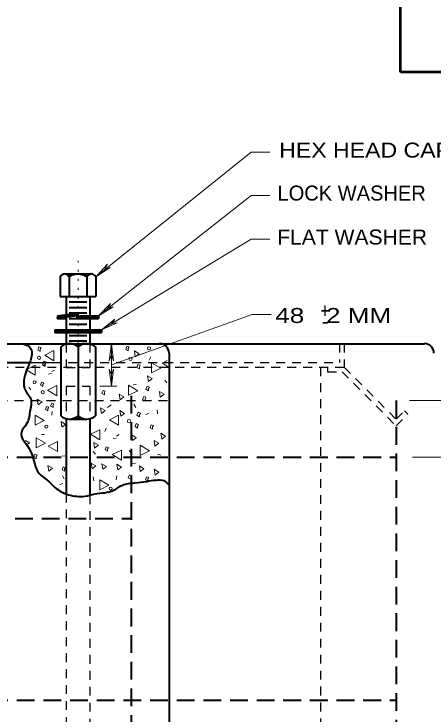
# Model space of a CAD drawing. Extents: x 312583 to 312854, y 144419 to 144597.
# Drawn here: x 312647.35 to 312668.62, y 144453.61 to 144489.11 of the extents above; entities that cross this region are included whole.
import ezdxf

# ---------------------------------------------------------------- set-up
doc = ezdxf.new("R2010")
doc.units = 0
doc.header["$LTSCALE"] = 0.3
for name, pattern in [('DOTTED', [1.5, 0.3, -1.2]), ('MEDIUM_DASHED', [4.5, 3, -1.5]), ('SHORT_DASHED', [2.7, 1.5, -1.2])]:
    doc.linetypes.add(name, pattern=pattern)
doc.layers.add('1', color=7, linetype='Continuous', lineweight=13)

msp = doc.modelspace()

# ---------------------------------------------------------------- linework, layer by layer
at = {"layer": '1', "lineweight": 53}
for p, q in [((312666.9226, 144486.1644), (312666.9226, 144523.38)), ((312693.5008, 144486.1644), (312666.9226, 144486.1644))]:
    msp.add_line(p, q, dxfattribs=at)
at = {"layer": '1'}
for p, q in [((312651.4874, 144475.7878), (312659.3534, 144482.1128)), ((312660.3117, 144482.1128), (312659.3534, 144482.1128)), ((312651.633, 144473.8021), (312659.3534, 144479.9048)), ((312660.3117, 144479.9048), (312659.3534, 144479.9048)), ((312651.771, 144473.0968), (312659.3534, 144477.6968)), ((312660.3117, 144477.6968), (312659.3534, 144477.6968)), ((312651.4874, 144475.7878), (312652.0854, 144476.4241)), ((312652.0854, 144476.4241), (312651.9474, 144476.1634)), ((312651.4874, 144475.7878), (312652.2234, 144476.2554)), ((312652.2234, 144476.2554), (312651.9474, 144476.1634)), ((312651.633, 144473.8021), (312652.2387, 144474.4308)), ((312652.2387, 144474.4308), (312652.0854, 144474.1778)), ((312651.633, 144473.8021), (312652.369, 144474.2621)), ((312652.369, 144474.2621), (312652.0854, 144474.1778)), ((312651.771, 144473.0968), (312652.461, 144473.6334)), ((312652.277, 144471.3258), (312659.4125, 144473.879)), ((312652.461, 144473.6334), (312652.277, 144473.4034)), ((312660.3708, 144473.879), (312659.4125, 144473.879)), ((312651.771, 144473.0968), (312652.5684, 144473.4494)), ((312652.5684, 144473.4494), (312652.277, 144473.4034)), ((312647.93, 144472.3914), (312647.9377, 144472.2994)), ((312647.9607, 144472.2918), (312648.0987, 144472.3914)), ((312652.277, 144472.3914), (312652.1697, 144471.5251)), ((312652.277, 144470.2294), (312652.277, 144472.3914)), ((312652.277, 144472.3914), (312652.3844, 144471.5251)), ((312652.875, 144472.3838), (312652.875, 144472.3914)), ((312652.1697, 144471.5251), (312652.277, 144471.8011)), ((312652.3844, 144471.5251), (312652.277, 144471.8011)), ((312654.2704, 144471.7244), (312654.1937, 144471.5558)), ((312652.1697, 144471.0958), (312652.277, 144470.8198)), ((312652.277, 144470.2294), (312652.1697, 144471.0958)), ((312652.3844, 144471.0958), (312652.277, 144470.8198)), ((312652.277, 144470.2294), (312652.3844, 144471.0958)), ((312647.999, 144471.0421), (312648.4207, 144470.7891)), ((312649.0954, 144470.8504), (312649.241, 144470.8734)), ((312649.264, 144470.9808), (312649.3944, 144471.0498)), ((312654.9834, 144470.5361), (312655.083, 144470.3981)), ((312648.091, 144470.1911), (312648.1984, 144470.0531)), ((312651.472, 144470.0224), (312651.5027, 144470.0148)), ((312651.6944, 144470.2294), (312652.5607, 144470.2294)), ((312653.381, 144470.2984), (312653.5344, 144470.3138)), ((312653.4194, 144469.3248), (312653.5114, 144469.1561)), ((312671.3364, 144469.5164), (312667.388, 144469.5164)), ((312649.2564, 144468.7651), (312649.2794, 144468.9568)), ((312652.2694, 144469.2864), (312652.0854, 144469.1484)), ((312654.5924, 144469.0334), (312654.6154, 144468.8264)), ((312654.025, 144468.8034), (312654.1707, 144468.8418)), ((312652.0164, 144468.0981), (312651.9397, 144467.9294)), ((312648.7427, 144467.7838), (312648.8884, 144467.7914)), ((312652.369, 144467.5768), (312652.5147, 144467.5998)), ((312652.5377, 144467.7071), (312652.668, 144467.7761)), ((312651.3647, 144466.9174), (312651.472, 144466.7794)), ((312653.174, 144466.9788), (312653.2967, 144466.8178)), ((312649.7624, 144466.6874), (312649.9157, 144466.6951)), ((312654.6077, 144466.7871), (312654.7764, 144466.7411)), ((312667.5337, 144466.6414), (312674.9397, 144466.6414)), ((312653.289, 144466.3194), (312653.5037, 144466.3348)), ((312649.8007, 144465.7061), (312649.8927, 144465.5374)), ((312651.3647, 144465.6371), (312651.3877, 144465.4301)), ((312652.53, 144465.4914), (312652.553, 144465.6831)), ((312649.6704, 144465.2538), (312649.816, 144465.2998))]:
    msp.add_line(p, q, dxfattribs=at)
at = {"layer": '1', "linetype": 'DOTTED'}
msp.add_line((312650.5904, 144476.6004), (312650.5904, 144472.3914), dxfattribs=at)
at = {"layer": '1', "lineweight": 40}
for p, q in [((312649.6934, 144475.7878), (312649.6934, 144474.7911)), ((312649.9157, 144475.9258), (312651.265, 144475.9258)), ((312650.1457, 144475.7878), (312650.1457, 144474.7911)), ((312651.0427, 144475.7878), (312651.0427, 144474.7911)), ((312651.4874, 144475.7878), (312651.4874, 144474.7911)), ((312649.6934, 144474.7911), (312651.4874, 144474.7911)), ((312649.9924, 144474.7911), (312649.9924, 144472.3914)), ((312651.1884, 144474.7911), (312651.1884, 144472.3914)), ((312650.1457, 144474.5151), (312651.0427, 144474.5151)), ((312650.1457, 144474.2314), (312651.0427, 144474.2314)), ((312650.1457, 144473.9478), (312651.0427, 144473.9478)), ((312649.5554, 144473.8098), (312649.5554, 144473.6641)), ((312650.1457, 144473.6641), (312651.0427, 144473.6641)), ((312650.506, 144473.6641), (312651.633, 144473.6641)), ((312650.5444, 144473.8098), (312651.633, 144473.8098)), ((312651.633, 144473.8021), (312651.633, 144473.6641)), ((312650.1457, 144473.3804), (312651.0427, 144473.3804)), ((312649.4097, 144473.0968), (312651.771, 144473.0968)), ((312649.4097, 144473.0968), (312649.4097, 144472.9588)), ((312649.4097, 144473.0661), (312651.771, 144473.0661)), ((312649.4097, 144473.0278), (312651.771, 144473.0278)), ((312649.4097, 144472.9894), (312651.771, 144472.9894)), ((312649.4097, 144472.9588), (312651.771, 144472.9588)), ((312651.771, 144473.0968), (312651.771, 144472.9588)), ((312650.1457, 144472.8131), (312651.0427, 144472.8131)), ((312650.1457, 144472.5294), (312651.0427, 144472.5294)), ((312636.5144, 144472.3914), (312654.7227, 144472.3914)), ((312649.7164, 144472.2304), (312649.7164, 144468.7268)), ((312649.9924, 144472.3914), (312651.1884, 144472.3914)), ((312650.1534, 144472.3914), (312651.0274, 144472.3914)), ((312650.5904, 144472.3914), (312650.5904, 144468.5658)), ((312651.472, 144472.2304), (312651.472, 144468.7268)), ((312654.7227, 144472.3914), (312668.1394, 144472.3914)), ((312655.2057, 144471.9161), (312655.2057, 144448.7628)), ((312643.0924, 144471.4331), (312648.1217, 144471.4331)), ((312649.9924, 144468.5811), (312649.9924, 144464.7938)), ((312650.1534, 144468.5658), (312651.0274, 144468.5658)), ((312651.1884, 144468.5811), (312651.1884, 144464.7094))]:
    msp.add_line(p, q, dxfattribs=at)
at = {"layer": '1', "linetype": 'SHORT_DASHED', "lineweight": 25}
for p, q in [((312649.9924, 144472.3914), (312649.9924, 144471.1801)), ((312651.1884, 144472.3914), (312651.1884, 144471.1801)), ((312663.8307, 144472.3914), (312663.8307, 144471.4331)), ((312664.0684, 144472.3914), (312664.0684, 144471.1954)), ((312627.414, 144471.4331), (312663.8307, 144471.4331)), ((312648.1217, 144471.4331), (312649.7164, 144471.4331)), ((312627.1687, 144471.1954), (312664.0684, 144471.1954)), ((312649.9924, 144471.1801), (312651.1884, 144471.1801)), ((312662.8724, 144471.1954), (312662.8724, 144449.3914)), ((312663.225, 144471.1954), (312663.225, 144470.9578)), ((312664.0684, 144471.1954), (312666.7057, 144468.5581)), ((312663.225, 144470.9578), (312663.9687, 144470.9578)), ((312663.9687, 144470.9578), (312666.7057, 144468.2208)), ((312649.9924, 144470.2294), (312651.1884, 144470.2294)), ((312649.9924, 144470.2294), (312649.9924, 144468.5811)), ((312651.1884, 144470.2294), (312651.1884, 144468.5811)), ((312636.039, 144469.5164), (312655.2057, 144469.5164)), ((312666.7057, 144468.5581), (312667.1274, 144468.9798)), ((312667.1274, 144468.9798), (312667.296, 144468.8111)), ((312666.7057, 144468.2208), (312667.296, 144468.8111)), ((312649.9924, 144464.7938), (312649.9924, 144436.6878)), ((312651.1884, 144464.7094), (312651.1884, 144436.6878))]:
    msp.add_line(p, q, dxfattribs=at)
at = {"layer": '1', "linetype": 'MEDIUM_DASHED', "lineweight": 40}
for p, q in [((312653.289, 144469.7541), (312653.289, 144448.7628)), ((312666.7057, 144469.5164), (312666.7057, 144451.3541)), ((312624.539, 144466.6414), (312666.7057, 144466.6414)), ((312637.9557, 144463.5288), (312653.289, 144463.5288)), ((312624.539, 144454.3134), (312666.7057, 144454.3134))]:
    msp.add_line(p, q, dxfattribs=at)
at = {"layer": '1', "lineweight": 40}
for points in [[(312649.977, 144475.9258), (312650.4754, 144475.9181), (312650.391, 144475.9028), (312650.3374, 144475.8951), (312650.2377, 144475.8568), (312650.1457, 144475.7954), (312650.115, 144475.8491), (312650.069, 144475.8798), (312649.9924, 144475.9181), (312650.437, 144475.9181), (312650.3067, 144475.8951), (312650.2224, 144475.8491), (312650.1534, 144475.8031), (312650.0767, 144475.8721), (312650.023, 144475.9104), (312650.3834, 144475.9104), (312650.2607, 144475.8721), (312650.1534, 144475.8184), (312650.0537, 144475.9028), (312650.3374, 144475.9104), (312650.1457, 144475.8261), (312650.069, 144475.8951), (312650.3067, 144475.9028), (312650.138, 144475.8414), (312650.0844, 144475.8951), (312650.276, 144475.8951), (312650.1457, 144475.8568), (312650.1074, 144475.8874), (312650.2224, 144475.8874), (312650.1534, 144475.8644), (312650.1304, 144475.8798), (312650.184, 144475.8798), (312650.1457, 144475.8721)], [(312651.2114, 144475.9258), (312650.7054, 144475.9181), (312650.7897, 144475.9028), (312650.851, 144475.8951), (312650.943, 144475.8568), (312651.035, 144475.7954), (312651.0734, 144475.8491), (312651.1117, 144475.8798), (312651.1884, 144475.9181), (312650.7437, 144475.9181), (312650.874, 144475.8951), (312650.966, 144475.8491), (312651.035, 144475.8031), (312651.104, 144475.8721), (312651.1577, 144475.9104), (312650.7974, 144475.9104), (312650.92, 144475.8721), (312651.035, 144475.8184), (312651.1347, 144475.9028), (312650.8434, 144475.9104), (312651.035, 144475.8261), (312651.1117, 144475.8951), (312650.874, 144475.9028), (312651.0427, 144475.8414), (312651.0964, 144475.8951), (312650.9124, 144475.8951), (312651.035, 144475.8568), (312651.0734, 144475.8874), (312650.9584, 144475.8874), (312651.0274, 144475.8644), (312651.0504, 144475.8798), (312650.9967, 144475.8798), (312651.035, 144475.8721)], [(312649.5554, 144473.8098), (312650.5904, 144473.9478), (312650.506, 144473.6641)], [(312649.9924, 144473.6641), (312649.5554, 144473.6794), (312649.5707, 144473.7944), (312650.5597, 144473.9248), (312650.529, 144473.8174), (312649.9847, 144473.7408), (312649.977, 144473.6871), (312649.5784, 144473.7024), (312649.586, 144473.7714), (312650.5367, 144473.9018), (312650.5137, 144473.8328), (312649.9617, 144473.7408), (312649.954, 144473.7024), (312649.5937, 144473.7101), (312649.5937, 144473.7484), (312650.4984, 144473.8788), (312650.4984, 144473.8558), (312649.9694, 144473.7561), (312649.931, 144473.7408), (312649.8237, 144473.7178), (312649.6167, 144473.7331), (312650.4754, 144473.8634), (312649.7547, 144473.7254)], [(312650.5444, 144473.8098), (312649.5554, 144473.6641), (312649.9924, 144473.6641)], [(312650.529, 144473.6794), (312651.61, 144473.6794), (312651.61, 144473.7944), (312650.5674, 144473.7868), (312650.529, 144473.7024), (312651.5947, 144473.6948), (312651.587, 144473.7714), (312650.575, 144473.7638), (312650.552, 144473.7101), (312651.5717, 144473.7178), (312651.5564, 144473.7484), (312651.5487, 144473.7561), (312650.5827, 144473.7484), (312650.5674, 144473.7254), (312651.5487, 144473.7331)], [(312650.2684, 144472.3838), (312650.92, 144472.3838), (312650.8434, 144472.3684), (312650.7744, 144472.3531), (312650.7054, 144472.3224), (312650.6594, 144472.2994), (312650.598, 144472.2534), (312650.5904, 144472.2458), (312650.4677, 144472.3224), (312650.3604, 144472.3684), (312650.299, 144472.3838), (312650.874, 144472.3838), (312650.828, 144472.3761), (312650.7744, 144472.3608), (312650.7054, 144472.3378), (312650.6364, 144472.2994), (312650.6134, 144472.2764), (312650.5904, 144472.2534), (312650.483, 144472.3301), (312650.3604, 144472.3761), (312650.7897, 144472.3761), (312650.6824, 144472.3378), (312650.5904, 144472.2764), (312650.4064, 144472.3684), (312650.7437, 144472.3684), (312650.5904, 144472.2688), (312650.4447, 144472.3608), (312650.713, 144472.3608), (312650.598, 144472.2994), (312650.4984, 144472.3531), (312650.6747, 144472.3531), (312650.5904, 144472.3224), (312650.4907, 144472.3454), (312650.552, 144472.3071), (312650.5674, 144472.3454), (312650.5827, 144472.2918), (312650.6287, 144472.3378), (312650.6517, 144472.3378), (312650.6824, 144472.3454)], [(312650.2684, 144468.5734), (312650.92, 144468.5658), (312650.8434, 144468.5811), (312650.7744, 144468.6041), (312650.7054, 144468.6348), (312650.6594, 144468.6578), (312650.598, 144468.7038), (312650.5904, 144468.7114), (312650.4677, 144468.6348), (312650.3604, 144468.5888), (312650.299, 144468.5734), (312650.874, 144468.5734), (312650.828, 144468.5811), (312650.7744, 144468.5888), (312650.7054, 144468.6194), (312650.6364, 144468.6578), (312650.6134, 144468.6731), (312650.5904, 144468.6961), (312650.483, 144468.6271), (312650.3604, 144468.5811), (312650.7897, 144468.5811), (312650.6824, 144468.6194), (312650.5904, 144468.6731), (312650.4064, 144468.5888), (312650.7437, 144468.5811), (312650.5904, 144468.6884), (312650.4447, 144468.5964), (312650.713, 144468.5888), (312650.598, 144468.6578), (312650.4984, 144468.6041), (312650.6747, 144468.6041), (312650.5904, 144468.6271), (312650.4907, 144468.6118), (312650.552, 144468.6501), (312650.5674, 144468.6118), (312650.5827, 144468.6654), (312650.6287, 144468.6194), (312650.6517, 144468.6194), (312650.6824, 144468.6118)]]:
    msp.add_lwpolyline(points, dxfattribs=at)
at = {"layer": '1'}
for points in [[(312648.6737, 144472.1078), (312648.7197, 144472.1921), (312648.6047, 144472.2228), (312648.551, 144472.0694), (312648.6737, 144472.0004)], [(312653.1357, 144472.1384), (312653.1817, 144472.2228), (312653.0667, 144472.2534), (312653.0054, 144472.1001), (312653.1357, 144472.0311)], [(312649.3714, 144471.5251), (312649.3714, 144472.0388), (312648.9037, 144471.8088)], [(312653.4884, 144471.7321), (312653.68, 144471.8778), (312653.45, 144472.0234)], [(312653.6954, 144471.2184), (312653.7414, 144471.3028), (312653.6264, 144471.3334), (312653.565, 144471.1801), (312653.6954, 144471.1111)], [(312654.3164, 144471.4178), (312654.3164, 144470.9041), (312654.784, 144471.1418)], [(312654.1554, 144470.4748), (312654.347, 144470.6204), (312654.117, 144470.7584)], [(312648.8117, 144470.3214), (312648.8654, 144470.4058), (312648.7427, 144470.4364), (312648.689, 144470.2831), (312648.8117, 144470.2141)], [(312649.517, 144469.7541), (312649.517, 144470.2678), (312649.0494, 144470.0378)], [(312651.9244, 144469.9074), (312651.9704, 144469.9841), (312651.8554, 144470.0224), (312651.794, 144469.8691), (312651.9244, 144469.8001)], [(312653.151, 144470.2908), (312653.151, 144469.7771), (312653.6187, 144470.0071)], [(312654.163, 144470.1144), (312654.209, 144470.1911), (312654.094, 144470.2294), (312654.0327, 144470.0761), (312654.163, 144470.0071)], [(312652.7217, 144469.5471), (312652.9134, 144469.6928), (312652.6757, 144469.8384)], [(312653.9867, 144469.5931), (312654.0327, 144469.6698), (312653.9177, 144469.7081), (312653.8564, 144469.5548), (312653.9867, 144469.4858)], [(312654.7534, 144469.6774), (312654.945, 144469.8231), (312654.715, 144469.9611)], [(312648.5664, 144469.2941), (312648.7657, 144469.4398), (312648.528, 144469.5778)], [(312649.3254, 144469.2558), (312649.3714, 144469.3401), (312649.2564, 144469.3784), (312649.195, 144469.2251), (312649.3254, 144469.1561)], [(312649.057, 144469.0871), (312649.1107, 144469.1638), (312648.988, 144469.2021), (312648.9344, 144469.0488), (312649.057, 144468.9798)], [(312651.771, 144468.8571), (312651.9627, 144469.0028), (312651.7327, 144469.1408)], [(312652.7524, 144468.7114), (312652.944, 144468.8571), (312652.714, 144468.9951)], [(312648.413, 144468.7651), (312648.413, 144468.2514), (312648.8807, 144468.4891)], [(312652.645, 144468.2514), (312652.645, 144468.7651), (312652.1774, 144468.5351)], [(312653.703, 144468.7881), (312653.749, 144468.8724), (312653.634, 144468.9108), (312653.5727, 144468.7574), (312653.703, 144468.6884)], [(312649.77, 144468.1518), (312649.9617, 144468.2974), (312649.7317, 144468.4431)], [(312653.6034, 144468.2131), (312653.657, 144468.2974), (312653.5344, 144468.3358), (312653.4807, 144468.1824), (312653.6034, 144468.1134)], [(312654.37, 144468.1594), (312654.416, 144468.2438), (312654.301, 144468.2821), (312654.2474, 144468.1288), (312654.37, 144468.0598)], [(312651.6944, 144467.5154), (312651.6944, 144468.0291), (312651.2267, 144467.7991)], [(312648.4667, 144467.6228), (312648.4667, 144467.1091), (312648.9344, 144467.3391)], [(312653.3504, 144467.4771), (312653.542, 144467.6228), (312653.312, 144467.7684)], [(312654.83, 144467.5538), (312655.0217, 144467.6994), (312654.7917, 144467.8451)], [(312649.5477, 144466.9174), (312649.5477, 144467.4311), (312649.08, 144467.2011)], [(312651.426, 144467.0938), (312651.6254, 144467.2394), (312651.3877, 144467.3774)], [(312653.7414, 144467.2394), (312653.7414, 144466.7181), (312654.209, 144466.9558)], [(312654.485, 144467.1934), (312654.6844, 144467.3391), (312654.4467, 144467.4771)], [(312652.0854, 144467.0478), (312652.139, 144467.1321), (312652.0164, 144467.1628), (312651.9627, 144467.0094), (312652.0854, 144466.9404)], [(312652.7907, 144466.4804), (312652.7907, 144466.9941), (312652.323, 144466.7641)], [(312648.4667, 144466.6644), (312648.5127, 144466.7411), (312648.3977, 144466.7794), (312648.3364, 144466.6261), (312648.4667, 144466.5571)], [(312649.103, 144465.9284), (312649.2947, 144466.0741), (312649.057, 144466.2198)], [(312649.908, 144466.0281), (312649.954, 144466.1048), (312649.839, 144466.1431), (312649.7854, 144465.9898), (312649.908, 144465.9208)], [(312651.3034, 144466.0434), (312651.495, 144466.1891), (312651.2574, 144466.3271)], [(312651.84, 144466.0204), (312652.0394, 144466.1661), (312651.8017, 144466.3041)], [(312652.599, 144465.9898), (312652.7907, 144466.1354), (312652.553, 144466.2811)], [(312653.7337, 144465.9054), (312653.9254, 144466.0511), (312653.6954, 144466.1891)], [(312653.266, 144465.6294), (312653.312, 144465.7061), (312653.1894, 144465.7444), (312653.1357, 144465.5911), (312653.266, 144465.5221)], [(312654.4927, 144465.7291), (312654.6844, 144465.8748), (312654.4467, 144466.0204)], [(312651.6867, 144465.4914), (312651.6867, 144464.9778), (312652.1544, 144465.2154)], [(312654.1324, 144465.5298), (312654.1784, 144465.6064), (312654.0634, 144465.6448), (312654.002, 144465.4914), (312654.1324, 144465.4224)]]:
    msp.add_lwpolyline(points, close=True, dxfattribs=at)
at = {"layer": '1', "linetype": 'SHORT_DASHED', "lineweight": 25}
msp.add_lwpolyline([(312648.9267, 144471.3641), (312648.9727, 144471.4484), (312648.8577, 144471.4791), (312648.7964, 144471.3258), (312648.9267, 144471.2568)], close=True, dxfattribs=at)
at = {"layer": '1'}
for points in [[(312655.0984, 144471.5404), (312654.8454, 144471.4101), (312655.198, 144471.2031)], [(312648.4207, 144470.7891), (312648.4207, 144471.3028), (312648.0144, 144471.0958)], [(312648.022, 144467.2778), (312648.1294, 144467.3544), (312647.9224, 144467.4848)]]:
    msp.add_lwpolyline(points, dxfattribs=at)
for centre, radius in [((312654.1849, 144472.1588), 0.0784), ((312648.617, 144471.6729), 0.0784), ((312653.2496, 144471.6183), 0.0784), ((312648.3879, 144470.4347), 0.0784), ((312648.801, 144469.9307), 0.0784), ((312648.984, 144468.1874), 0.0784), ((312653.1742, 144468.4615), 0.0865), ((312652.2388, 144465.0428), 0.0784)]:
    msp.add_circle(centre, radius, dxfattribs=at)
at = {"layer": '1', "lineweight": 40}
for centre, radius, start, end in [((312649.917, 144475.6772), 0.2489, 25.60064, 154.39936), ((312650.5904, 144475.1425), 0.7836, 55.04559, 124.95441), ((312651.2638, 144475.6772), 0.2489, 25.60064, 154.39936), ((312650.1521, 144471.7103), 0.6817, 50.00693, 129.99306), ((312651.0284, 144471.7103), 0.6817, 50.00694, 129.99307), ((312654.7227, 144471.9132), 0.4792, 0, 90), ((312668.1394, 144471.9132), 0.4792, 0, 90), ((312650.1521, 144469.2472), 0.6817, 230.00694, 309.99307), ((312651.0284, 144469.2472), 0.6817, 230.00693, 309.99306)]:
    msp.add_arc(centre, radius, start, end, dxfattribs=at)
msp.add_spline([(312647.7537, 144472.3914), (312648.206, 144472.1308), (312648.2444, 144471.8318), (312648.0604, 144471.2338), (312647.838, 144470.4134), (312648.022, 144469.8538), (312648.1677, 144469.6621), (312648.1677, 144469.0258), (312647.9837, 144468.3204), (312647.723, 144467.9064), (312648.1677, 144466.9711), (312648.62, 144465.8134), (312649.0264, 144465.4761), (312649.402, 144465.1081), (312650.115, 144464.7324), (312650.9354, 144464.6558), (312651.4567, 144464.7708), (312652.392, 144464.9548), (312652.8367, 144465.2154), (312653.473, 144465.3304), (312654.071, 144465.4071), (312654.5617, 144465.4761), (312654.9297, 144465.4454), (312655.2057, 144465.2154)], degree=3, dxfattribs=at)

# ---------------------------------------------------------------- texts
at = {"layer": '1'}
for s, width, p in [('HEX HEAD CAP SCR.', 1.15, (312660.7794, 144481.8281)), ('FLAT WASHER', 1.05, (312660.6797, 144477.4198)), ('+', 0.8, (312662.8666, 144473.6939)), ('48   2 MM', 1.3, (312660.58, 144473.4408))]:
    msp.add_text(s, height=0.76, dxfattribs=dict(at, width=width)).set_placement(p)
for s, p in [('LOCK WASHER', (312660.695, 144479.6508)), ('-', (312662.9437, 144473.1532))]:
    msp.add_text(s, height=0.76, dxfattribs=at).set_placement(p)

doc.saveas('drawing.dxf')
